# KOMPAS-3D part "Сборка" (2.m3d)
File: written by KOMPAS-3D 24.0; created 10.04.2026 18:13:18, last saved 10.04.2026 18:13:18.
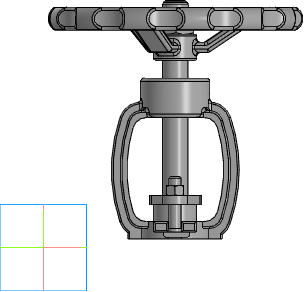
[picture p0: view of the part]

Document properties: Автор: R2D2; Полное имя файла: E:\Работа\Зайцев\VSO3131M-F-S Клапан запорный DN.ru Ду15-100 Ру40\DN20\исходные материалы\2.m3d

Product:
- Part/product: Сборка
    Масса: 1.44705

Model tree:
1. Операция без истории:1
